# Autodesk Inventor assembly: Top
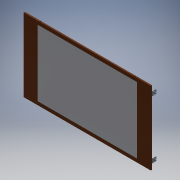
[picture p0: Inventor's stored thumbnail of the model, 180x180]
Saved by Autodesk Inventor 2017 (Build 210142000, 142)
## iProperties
Created: 2017-05
Part Number: Top
Document SubType Name: Assembly
Designer: Savy
Author: Savy
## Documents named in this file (10)
- D:\3D Printer Designs\John Ledden Designs\Infinity Mirror Table\SavanDrawings\Top.iam
- D:\3D Printer Designs\John Ledden Designs\Infinity Mirror Table\SavanDrawings\OneWayAcrylic.ipt
- D:\3D Printer Designs\John Ledden Designs\Infinity Mirror Table\SavanDrawings\TopSidePanel_Long.ipt
- D:\3D Printer Designs\John Ledden Designs\Infinity Mirror Table\SavanDrawings\TopSidePanel_Short.ipt
- D:\3D Printer Designs\John Ledden Designs\Infinity Mirror Table\SavanDrawings\TopCutout_Cover.ipt
- D:\3D Printer Designs\John Ledden Designs\Infinity Mirror Table\SavanDrawings\8_Screw_1inch.ipt
- D:\3D Printer Designs\John Ledden Designs\Infinity Mirror Table\SavanDrawings\17715A430_BRACKET_step.ipt
- D:\3D Printer Designs\John Ledden Designs\Infinity Mirror Table\SavanDrawings\TopGlass.ipt
- D:\3D Printer Designs\John Ledden Designs\Infinity Mirror Table\SavanDrawings\8_Screw_-5inch.ipt
- D:\3D Printer Designs\John Ledden Designs\Infinity Mirror Table\SavanDrawings\TapeStrip.ipt
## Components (36 placed, 36 different names)
1. OneWayAcrylic_1291
2. TopSidePanel_Long_1292
3. TopSidePanel_Short_1293
4. TopSidePanel_Short_1294
5. TopSidePanel_Long_1295
6. TopCutout_Cover_1296
7. 8_Screw_1inch_1297
8. 8_Screw_1inch_1298
9. 8_Screw_1inch_1299
10. 8_Screw_1inch_1300
11. 8_Screw_1inch_1301
12. 8_Screw_1inch_1302
13. 8_Screw_1inch_1303
14. 8_Screw_1inch_1304
15. 17715A430_BRACKET_step_1305
16. 17715A430_BRACKET_step_1306
17. 17715A430_BRACKET_step_1307
18. 17715A430_BRACKET_step_1308
19. TopCutout_Cover_1309
20. TopGlass_1310
21. 8_Screw_-5inch_1311
22. 8_Screw_-5inch_1312
23. 8_Screw_-5inch_1313
24. 8_Screw_-5inch_1314
25. 8_Screw_-5inch_1315
26. 8_Screw_-5inch_1316
27. 8_Screw_-5inch_1317
28. 8_Screw_-5inch_1318
29. 8_Screw_-5inch_1319
30. 8_Screw_-5inch_1320
31. 8_Screw_-5inch_1321
32. 8_Screw_-5inch_1322
33. TapeStrip_1335
34. TapeStrip_1336
35. TapeStrip_1337
36. TapeStrip_1338
